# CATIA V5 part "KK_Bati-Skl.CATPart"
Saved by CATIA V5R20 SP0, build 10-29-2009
Part number: Bati-Skl
Publications: "Taille du joug"
Bounding box of the stored display mesh (mm): x -99.999 to 99.999, y -86.772 to 86.772, z 0 to 0
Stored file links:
  G:\Khaled_CFAO_2011\ST2M\ST2M_GR1\msallin\Khaled\Version_Finale\KK_Bati-Skl.CATPart
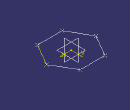
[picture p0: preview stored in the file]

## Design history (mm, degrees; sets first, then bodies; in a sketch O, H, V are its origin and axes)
Parameters
  `Taille du joug` = 100 mm
Set1
  Line1: type PtPt, FirstPoint vertex [element of Sketch1 | element of Sketch1], SecondPoint vertex [element of Sketch1 | element of Sketch1]
  Line2: type PtPt, FirstPoint vertex [element of Sketch1 | element of Sketch1], SecondPoint vertex [element of Sketch1 | element of Sketch1]
  Line3: type PtPt, FirstPoint vertex [element of Sketch1 | element of Sketch1], SecondPoint vertex [element of Sketch1 | element of Sketch1]
  Line4: type PtPt, FirstPoint vertex [element of Sketch1 | element of Sketch1], SecondPoint vertex [element of Sketch1 | element of Sketch1]
  Line5: type PtPt, FirstPoint vertex [element of Sketch1 | element of Sketch1], SecondPoint vertex [element of Sketch1 | element of Sketch1]
  Line6: type PtPt, FirstPoint vertex [element of Sketch1 | element of Sketch1], SecondPoint vertex [element of Sketch1 | element of Sketch1]
  Point1: (0, 0, 0), relative to vertex of Line1
  Point2: (0, 0, 0), relative to vertex of Line1
  Point3: (0, 0, 0), relative to vertex of Line2
  Point4: (0, 0, 0), relative to vertex of Line3
  Point5: (0, 0, 0), relative to vertex of Line4
  Point6: (0, 0, 0), relative to vertex of Line5
  Line7: type PtPt, FirstPoint Point1, SecondPoint Sketch1.O
  Line8: type PtPt, FirstPoint Point2, SecondPoint Sketch1.O
  Line9: type PtPt, FirstPoint Point3, SecondPoint Sketch1.O
  Line10: type PtPt, FirstPoint Point4, SecondPoint Sketch1.O
  Line11: type PtPt, FirstPoint Point5, SecondPoint Sketch1.O
  Line12: type PtPt, FirstPoint Point6, SecondPoint vertex of Line7
Body1 (main body)
  Sketch1 on xy-plane, origin (0, 0, 0), H (1, 0, 0), V (0, 1, 0)
    point P1 (-99.9994, -0.3398)
    point P2 (-49.7054, -86.7719)
    point P3 (50.294, -86.4321)
    point P4 (99.9994, 0.3398)
    point P5 (49.7054, 86.7719)
    point P6 (-50.294, 86.4321)
    point P7 (-74.8524, -43.5559)
    line L1 (-99.9994, -0.3398) -> (-49.7054, -86.7719)
    line L2 (-49.7054, -86.7719) -> (50.294, -86.4321)
    line L3 (50.294, -86.4321) -> (99.9994, 0.3398)
    line L4 (99.9994, 0.3398) -> (49.7054, 86.7719)
    line L5 (49.7054, 86.7719) -> (-50.294, 86.4321)
    line L6 (-50.294, 86.4321) -> (-99.9994, -0.3398)
    construction line L7 (0, 0) -> (-74.8524, -43.5559)
    construction circle A1 centre (0, 0) radius 100
    construction arc A2 centre (49.7054, 86.7719) radius 100 from (99.9994, 0.3398) to (-50.294, 86.4321) cw
    construction arc A3 centre (-49.7054, -86.7719) radius 100 from (50.294, -86.4321) to (-99.9994, -0.3398) ccw
    length L4 = 100 {= `Taille du joug`}
    coincidence: A1 P1, A1 P2, A1 P3, A1 P4, A1 P5, A1 P6, A2 O, A3 O
    midpoint: P7 L1
    parallelism: L1 L4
